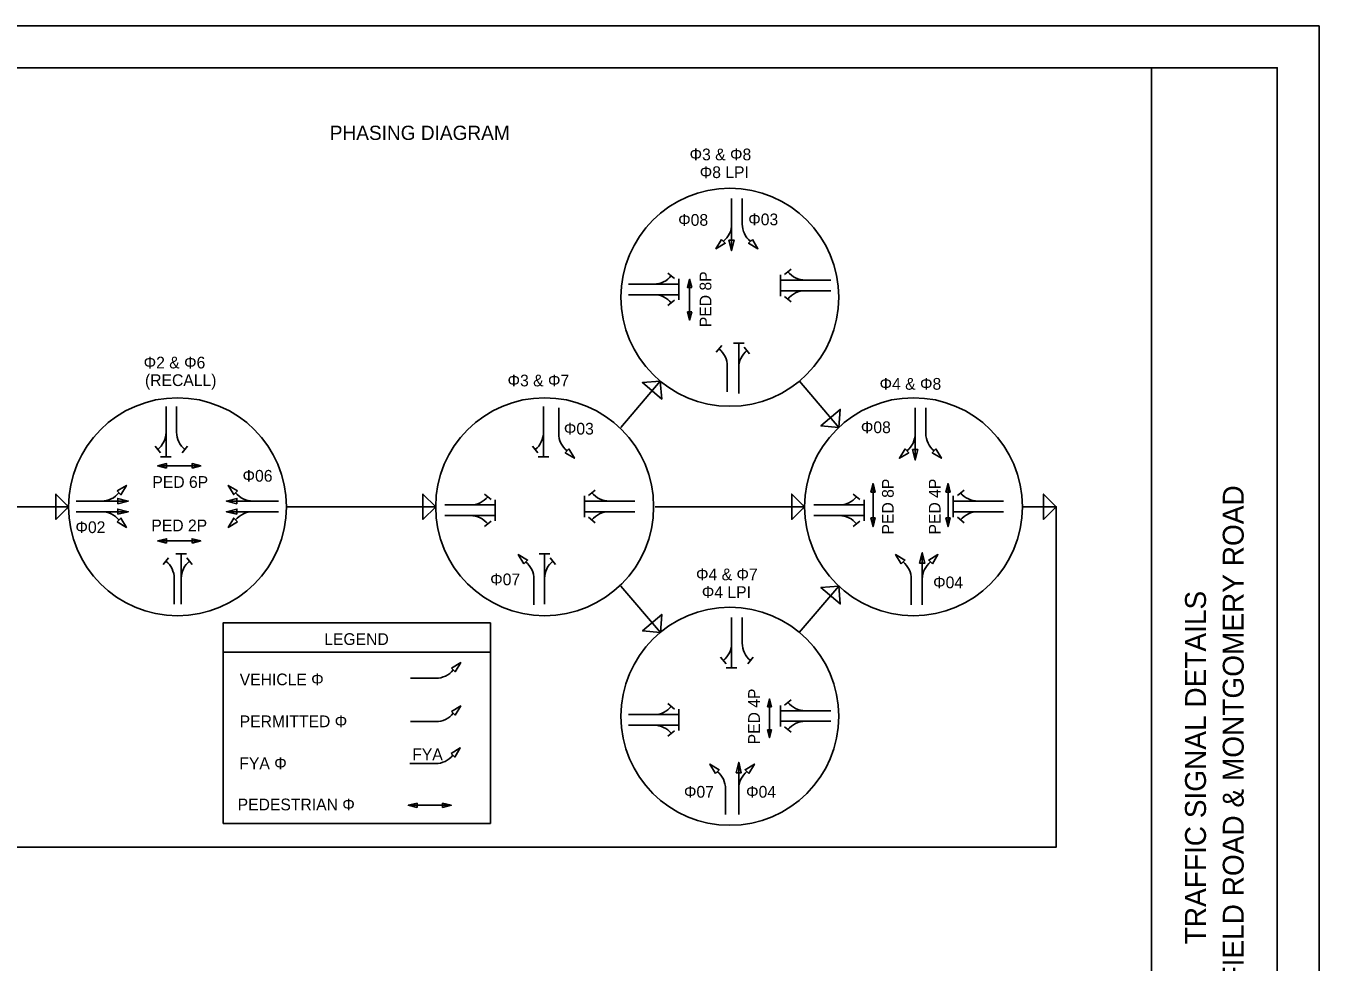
# Model space of a CAD drawing. Extents: x 0 to 34, y 0 to 22.
# Drawn here: x 18.57 to 34, y 10.83 to 22 of the extents above; entities that cross this region are included whole.
import ezdxf

# ---------------------------------------------------------------- set-up
doc = ezdxf.new("R2010")
doc.units = 0
for name, color, linetype in [('SG_P_Text', 7, 'Continuous'), ('SH_Border', 7, 'Continuous'), ('SH_Cut_Line', 7, 'Continuous'), ('SH_Data', 7, 'Continuous')]:
    doc.layers.add(name, color=color, linetype=linetype)

msp = doc.modelspace()

# ---------------------------------------------------------------- linework, layer by layer
at = {"layer": 'SG_P_Text'}
for p, q in [((26.99, 19.318), (26.99, 19.941)), ((26.99, 19.941), (26.99, 19.636)), ((27.116, 19.941), (27.116, 19.636)), ((26.31, 18.987), (26.23, 19.051)), ((26.359, 18.984), (26.359, 18.857)), ((27.573, 18.903), (27.573, 19.03)), ((27.622, 19.034), (27.702, 19.098)), ((25.758, 18.92), (26.359, 18.92)), ((25.758, 18.92), (26.064, 18.92)), ((26.359, 18.857), (26.359, 18.73)), ((26.489, 18.49), (26.489, 18.977)), ((28.174, 18.967), (27.573, 18.967)), ((27.573, 18.777), (27.573, 18.903)), ((28.174, 18.84), (27.573, 18.84)), ((28.174, 18.967), (27.868, 18.967)), ((28.174, 18.84), (27.868, 18.84)), ((25.758, 18.793), (26.359, 18.793)), ((25.758, 18.793), (26.064, 18.793)), ((26.31, 18.726), (26.23, 18.662)), ((27.622, 18.773), (27.702, 18.709)), ((27.011, 18.214), (27.138, 18.214)), ((27.074, 17.613), (27.074, 18.214)), ((26.871, 18.186), (26.807, 18.107)), ((27.141, 18.165), (27.205, 18.086)), ((26.938, 17.634), (26.938, 17.94)), ((27.074, 17.613), (27.074, 17.919)), ((26.139, 17.761), (25.669, 17.21)), ((28.269, 17.21), (27.798, 17.761)), ((20.241, 17.457), (20.241, 16.857)), ((20.241, 17.457), (20.241, 17.152)), ((20.367, 17.457), (20.367, 17.152)), ((24.745, 17.457), (24.745, 16.857)), ((24.745, 17.457), (24.745, 17.152)), ((24.927, 17.442), (24.927, 17.137)), ((29.18, 16.82), (29.18, 17.442)), ((29.18, 17.442), (29.18, 17.137)), ((29.306, 17.442), (29.306, 17.137)), ((20.174, 16.906), (20.11, 16.985)), ((20.434, 16.906), (20.498, 16.985)), ((24.678, 16.906), (24.614, 16.985)), ((20.177, 16.857), (20.304, 16.857)), ((24.682, 16.857), (24.809, 16.857)), ((20.143, 16.751), (20.656, 16.751)), ((28.677, 16.026), (28.677, 16.539)), ((29.572, 16.026), (29.572, 16.539)), ((24.121, 16.351), (24.041, 16.415)), ((25.234, 16.267), (25.234, 16.394)), ((25.283, 16.398), (25.362, 16.462)), ((28.521, 16.351), (28.441, 16.415)), ((29.634, 16.267), (29.634, 16.394)), ((29.683, 16.397), (29.763, 16.461)), ((19.079, 16.263), (17.298, 16.263)), ((19.791, 16.331), (19.168, 16.331)), ((19.168, 16.331), (19.473, 16.331)), ((19.791, 16.204), (19.168, 16.204)), ((19.168, 16.204), (19.473, 16.204)), ((20.961, 16.331), (21.583, 16.331)), ((20.961, 16.204), (21.583, 16.204)), ((21.583, 16.331), (21.278, 16.331)), ((21.583, 16.204), (21.278, 16.204)), ((23.459, 16.263), (21.678, 16.263)), ((23.569, 16.284), (24.169, 16.284)), ((23.569, 16.284), (23.874, 16.284)), ((24.169, 16.347), (24.169, 16.22)), ((24.169, 16.22), (24.169, 16.094)), ((25.835, 16.331), (25.234, 16.331)), ((25.234, 16.14), (25.234, 16.267)), ((25.835, 16.204), (25.234, 16.204)), ((25.835, 16.331), (25.529, 16.331)), ((25.835, 16.204), (25.529, 16.204)), ((27.859, 16.263), (26.079, 16.263)), ((27.969, 16.284), (28.57, 16.284)), ((27.969, 16.284), (28.275, 16.284)), ((28.57, 16.347), (28.57, 16.22)), ((28.57, 16.22), (28.57, 16.093)), ((30.235, 16.33), (29.634, 16.33)), ((29.634, 16.14), (29.634, 16.267)), ((30.235, 16.204), (29.634, 16.204)), ((30.235, 16.33), (29.929, 16.33)), ((30.235, 16.204), (29.929, 16.204)), ((23.569, 16.157), (24.169, 16.157)), ((23.569, 16.157), (23.874, 16.157)), ((24.121, 16.09), (24.041, 16.026)), ((25.283, 16.137), (25.362, 16.073)), ((27.969, 16.157), (28.57, 16.157)), ((27.969, 16.157), (28.275, 16.157)), ((28.521, 16.09), (28.441, 16.026)), ((29.683, 16.137), (29.763, 16.073)), ((20.143, 15.856), (20.656, 15.856)), ((20.272, 15.654), (20.208, 15.575)), ((20.36, 15.703), (20.486, 15.703)), ((20.423, 15.102), (20.423, 15.703)), ((20.49, 15.654), (20.554, 15.575)), ((24.694, 15.703), (24.821, 15.703)), ((24.757, 15.102), (24.757, 15.703)), ((24.824, 15.654), (24.888, 15.575)), ((29.264, 15.715), (29.264, 15.092)), ((20.339, 15.102), (20.339, 15.408)), ((20.423, 15.102), (20.423, 15.408)), ((24.631, 15.092), (24.631, 15.398)), ((24.757, 15.102), (24.757, 15.408)), ((26.14, 14.764), (25.669, 15.316)), ((28.269, 15.316), (27.797, 14.764)), ((29.134, 15.092), (29.134, 15.398)), ((26.99, 14.942), (26.99, 14.341)), ((26.99, 14.942), (26.99, 14.636)), ((27.116, 14.942), (27.116, 14.636)), ((20.921, 14.53), (24.111, 14.53)), ((26.923, 14.39), (26.859, 14.47)), ((27.183, 14.39), (27.247, 14.47)), ((23.157, 14.217), (23.462, 14.217)), ((26.926, 14.341), (27.053, 14.341)), ((26.31, 13.85), (26.23, 13.914)), ((27.443, 13.507), (27.443, 13.971)), ((27.573, 13.767), (27.573, 13.893)), ((27.622, 13.897), (27.702, 13.961)), ((25.758, 13.783), (26.359, 13.783)), ((25.758, 13.783), (26.064, 13.783)), ((26.359, 13.847), (26.359, 13.72)), ((28.174, 13.83), (27.573, 13.83)), ((27.573, 13.64), (27.573, 13.767)), ((28.174, 13.83), (27.868, 13.83)), ((23.157, 13.7), (23.462, 13.7)), ((25.758, 13.657), (26.359, 13.657)), ((25.758, 13.657), (26.064, 13.657)), ((26.31, 13.59), (26.23, 13.526)), ((26.359, 13.72), (26.359, 13.593)), ((28.174, 13.703), (27.573, 13.703)), ((27.622, 13.636), (27.702, 13.572)), ((28.174, 13.703), (27.868, 13.703)), ((23.152, 13.199), (23.457, 13.199)), ((27.074, 13.215), (27.074, 12.592)), ((26.917, 12.592), (26.917, 12.897)), ((27.074, 12.89), (27.074, 12.897)), ((23.645, 12.702), (23.132, 12.702))]:
    msp.add_line(p, q, dxfattribs=at)
for points in [[(26.868, 19.451), (26.802, 19.341), (26.913, 19.407)], [(27.237, 19.451), (27.304, 19.341), (27.193, 19.407)], [(26.958, 19.443), (26.99, 19.318), (27.021, 19.443)], [(26.514, 18.878), (26.489, 18.977), (26.464, 18.878)], [(26.514, 18.588), (26.489, 18.49), (26.464, 18.588)], [(26.139, 17.761), (25.926, 17.744), (26.156, 17.547)], [(28.269, 17.21), (28.055, 17.227), (28.285, 17.424)], [(25.048, 16.952), (25.114, 16.842), (25.004, 16.908)], [(29.059, 16.952), (28.992, 16.842), (29.103, 16.908)], [(29.148, 16.945), (29.18, 16.82), (29.211, 16.945)], [(29.428, 16.952), (29.494, 16.842), (29.383, 16.908)], [(20.247, 16.725), (20.143, 16.751), (20.247, 16.777)], [(20.552, 16.725), (20.656, 16.751), (20.552, 16.777)], [(19.658, 16.452), (19.768, 16.518), (19.702, 16.407)], [(21.094, 16.452), (20.983, 16.518), (21.049, 16.408)], [(28.703, 16.435), (28.677, 16.539), (28.651, 16.435)], [(29.598, 16.435), (29.572, 16.539), (29.546, 16.435)], [(19.079, 16.263), (18.927, 16.415), (18.927, 16.112)], [(19.666, 16.299), (19.791, 16.331), (19.666, 16.362)], [(21.086, 16.299), (20.961, 16.331), (21.086, 16.362)], [(23.459, 16.263), (23.307, 16.415), (23.307, 16.112)], [(27.859, 16.263), (27.708, 16.415), (27.708, 16.112)], [(30.864, 16.263), (30.713, 16.415), (30.713, 16.112)], [(19.666, 16.173), (19.791, 16.204), (19.666, 16.235)], [(21.086, 16.173), (20.961, 16.204), (21.086, 16.235)], [(19.658, 16.083), (19.768, 16.016), (19.702, 16.127)], [(21.094, 16.083), (20.983, 16.017), (21.049, 16.127)], [(28.703, 16.13), (28.677, 16.026), (28.651, 16.13)], [(29.598, 16.13), (29.572, 16.026), (29.546, 16.13)], [(20.247, 15.83), (20.143, 15.856), (20.247, 15.882)], [(20.552, 15.83), (20.656, 15.856), (20.552, 15.882)], [(24.51, 15.582), (24.444, 15.693), (24.555, 15.627)], [(29.013, 15.582), (28.947, 15.693), (29.057, 15.627)], [(29.233, 15.59), (29.264, 15.715), (29.296, 15.59)], [(29.385, 15.582), (29.452, 15.693), (29.341, 15.627)], [(28.269, 15.316), (28.055, 15.299), (28.285, 15.103)], [(26.14, 14.764), (25.927, 14.781), (26.157, 14.978)], [(24.111, 14.88), (20.923, 14.88), (20.923, 12.485), (24.111, 12.485)], [(23.647, 14.338), (23.757, 14.404), (23.691, 14.294)], [(27.466, 13.877), (27.443, 13.971), (27.419, 13.877)], [(23.647, 13.821), (23.757, 13.887), (23.691, 13.777)], [(27.466, 13.601), (27.443, 13.507), (27.419, 13.601)], [(23.642, 13.32), (23.752, 13.386), (23.686, 13.276)], [(26.796, 13.082), (26.73, 13.193), (26.84, 13.126)], [(27.043, 13.09), (27.074, 13.215), (27.105, 13.09)], [(27.195, 13.082), (27.261, 13.193), (27.151, 13.126)], [(23.236, 12.728), (23.132, 12.702), (23.236, 12.676)], [(23.541, 12.728), (23.645, 12.702), (23.541, 12.676)]]:
    msp.add_lwpolyline(points, close=True, dxfattribs=at)
msp.add_lwpolyline([(30.458, 16.263), (30.864, 16.263), (30.864, 12.202), (14.698, 12.202), (14.292, 12.202), (14.292, 16.263), (14.698, 16.263)], dxfattribs=at)
for centre in [(26.969, 18.762), (20.378, 16.263), (24.759, 16.263), (29.159, 16.263), (26.969, 13.763)]:
    msp.add_circle(centre, 1.3, dxfattribs=at)
for centre, start, end in [((26.725, 19.636), 308.7993, 0), ((27.381, 19.636), 180, 231.2007), ((26.064, 19.185), 270, 321.2007), ((27.868, 19.232), 218.7864, 269.9871), ((27.868, 18.575), 90.0129, 141.2136), ((26.064, 18.528), 38.7993, 90), ((26.673, 17.94), 360, 51.2007), ((27.339, 17.919), 128.7993, 180), ((19.976, 17.152), 308.7993, 0), ((20.632, 17.152), 180, 231.2007), ((24.48, 17.152), 308.7993, 0), ((25.192, 17.137), 180, 231.2007), ((28.915, 17.137), 308.7993, 0), ((29.572, 17.137), 180, 231.2007), ((19.473, 16.596), 270, 321.2007), ((21.278, 16.596), 218.7864, 269.9871), ((23.874, 16.549), 270, 321.2007), ((25.529, 16.596), 218.7993, 270), ((28.275, 16.549), 270, 321.2007), ((29.929, 16.595), 218.7993, 270), ((19.473, 15.939), 38.7864, 89.9871), ((21.278, 15.939), 90, 141.2007), ((25.529, 15.939), 90, 141.2007), ((29.929, 15.939), 90, 141.2007), ((23.874, 15.892), 38.7993, 90), ((28.275, 15.892), 38.7993, 90), ((20.074, 15.408), 360, 51.2007), ((20.688, 15.408), 128.7993, 180), ((24.366, 15.398), 360, 51.2007), ((25.023, 15.408), 128.7993, 180), ((28.869, 15.398), 360, 51.2007), ((29.529, 15.398), 128.7993, 178.779), ((26.725, 14.636), 308.7993, 0), ((27.381, 14.636), 180, 231.2007), ((23.462, 14.482), 270.0129, 321.2136), ((27.868, 14.095), 218.7864, 269.9871), ((23.462, 13.965), 270, 321.2007), ((26.064, 14.048), 270, 321.2007), ((26.064, 13.392), 38.7993, 90), ((27.868, 13.438), 90.0129, 141.2136), ((23.457, 13.464), 270, 321.2007), ((26.652, 12.897), 360, 51.2007), ((27.339, 12.897), 128.7993, 180)]:
    msp.add_arc(centre, 0.265, start, end, dxfattribs=at)
at = {"layer": 'SH_Border'}
msp.add_line((32, 0.5), (32, 21.5), dxfattribs=at)
msp.add_lwpolyline([(1.5, 21.5), (33.5, 21.5), (33.5, 0.5), (1.5, 0.5)], close=True, dxfattribs=at)
at = {"layer": 'SH_Cut_Line'}
msp.add_lwpolyline([(0, 0), (34, 0), (34, 22), (0, 22)], close=True, dxfattribs=at)

# ---------------------------------------------------------------- texts
at = {"layer": 'SG_P_Text'}
for s, height, p in [('PHASING DIAGRAM', 0.17, (22.195, 20.639)), ('Φ3 & Φ8', 0.14, (26.488, 20.396)), ('Φ8 LPI', 0.14, (26.609, 20.184)), ('Φ08', 0.14, (26.352, 19.615)), ('Φ03', 0.14, (27.188, 19.621)), ('Φ2 & Φ6', 0.14, (19.974, 17.913)), ('(RECALL)', 0.14, (19.99, 17.703)), ('Φ3 & Φ7', 0.14, (24.316, 17.699)), ('Φ4 & Φ8', 0.14, (28.755, 17.659)), ('Φ03', 0.14, (24.988, 17.124)), ('Φ08', 0.14, (28.532, 17.141)), ('Φ06', 0.14, (21.154, 16.562)), ('PED 6P', 0.14, (20.078, 16.488)), ('Φ02', 0.14, (19.16, 15.949)), ('PED 2P', 0.14, (20.066, 15.97)), ('Φ07', 0.14, (24.109, 15.326)), ('Φ4 & Φ7', 0.14, (26.565, 15.386)), ('Φ04', 0.14, (29.394, 15.29)), ('Φ4 LPI', 0.14, (26.634, 15.175)), ('LEGEND', 0.14, (22.129, 14.614)), ('VEHICLE Φ', 0.14, (21.12, 14.133)), ('PERMITTED Φ', 0.14, (21.12, 13.633)), ('FYA Φ', 0.14, (21.116, 13.132)), ('FYA', 0.14, (23.179, 13.239)), ('Φ07', 0.14, (26.421, 12.792)), ('Φ04', 0.14, (27.162, 12.792)), ('PEDESTRIAN Φ', 0.14, (21.096, 12.641))]:
    msp.add_text(s, height=height, dxfattribs=at).set_placement(p)
for s, p in [('PED 8P', (26.748, 18.405)), ('PED 8P', (28.924, 15.932)), ('PED 4P', (29.483, 15.932)), ('PED 4P', (27.327, 13.428))]:
    msp.add_text(s, height=0.14, rotation=90, dxfattribs=at).set_placement(p)
at = {"layer": 'SH_Data'}
for s, p in [('PLAINFIELD ROAD & MONTGOMERY ROAD', (33.1, 9.609)), ('TRAFFIC SIGNAL DETAILS', (32.65, 11.043))]:
    msp.add_text(s, height=0.25, rotation=90, dxfattribs=at).set_placement(p)

doc.saveas('drawing.dxf')
